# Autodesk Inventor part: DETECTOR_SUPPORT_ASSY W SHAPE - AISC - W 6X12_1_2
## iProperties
Shininess: 64.0
Length Units: 11272
Angle Units: 11279
Time Units: 11290
Mass Units: 11286
Length Display Precision: 3
Angle Display Precision: 2
Compacted: True
Part Number: DETECTOR_SUPPORT_ASSY W SHAPE - AISC - W 6X12_1_2
Document SubType Name: Modeling
Created: 2004-08
Designer: John Blackburn
Material: MILD_STEEL
Manufacturer: Standard
Standards Organization: Custom
Density: 0.0
Volumn: 0.0
Area: 0.0
PropertySet Name: Model Information
Control State: 0
Master: False
Checked Out: False
Author: John Blackburn
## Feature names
1. BaseExt [Extrusion]
2. Fillet1
